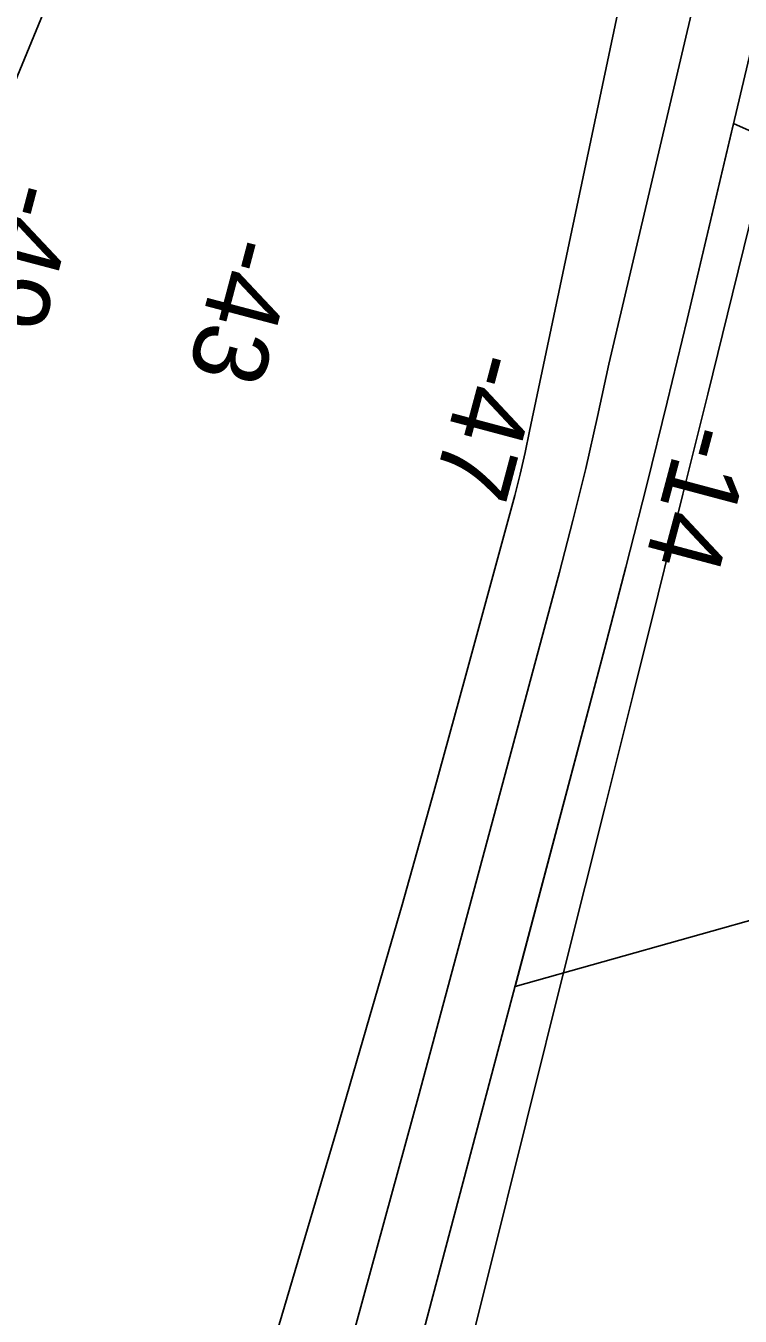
# Model space of a CAD drawing. Extents: x 3930721 to 3950824, y 220441 to 242861.
# Drawn here: x 3942447 to 3942767, y 232468 to 233046 of the extents above; entities that cross this region are included whole.
import ezdxf

# ---------------------------------------------------------------- set-up
doc = ezdxf.new("R2010")
doc.units = 0
for name, color, linetype in [('V-RIVR-RANG', 7, 'Continuous'), ('V-TOPO-DPTH', 7, 'Continuous'), ('V-TOPO-MAJR', 7, 'Continuous'), ('V-TOPO-MINR', 7, 'Continuous')]:
    doc.layers.add(name, color=color, linetype=linetype)

msp = doc.modelspace()

# ---------------------------------------------------------------- linework, layer by layer
at = {"layer": 'V-TOPO-DPTH'}
for points in [[(3942394.35, 231903.74), (3942586.24, 232551.54), (3942600.96, 232601.87), (3942615.46, 232652.28), (3942629.6, 232702.77), (3942643.52, 232753.34), (3942665.84, 232835.53), (3942668.29, 232845.07), (3942670.55, 232854.66), (3942672.53, 232864.32), (3942877.36, 233836.08), (3942881.48, 233843.98), (3943173.71, 234806.38)], [(3942394.35, 231903.74), (3942586.24, 232551.54), (3942600.96, 232601.87), (3942615.46, 232652.28), (3942629.6, 232702.77), (3942643.52, 232753.34), (3942665.84, 232835.53), (3942668.29, 232845.07), (3942670.55, 232854.66), (3942672.53, 232864.32), (3942877.36, 233836.08), (3942881.48, 233843.98), (3943173.71, 234806.38)], [(3943259.12, 234785.67), (3942961.54, 233812), (3942959.14, 233808.57), (3942932.99, 233722.43), (3942924.03, 233691.19), (3942915.71, 233659.79), (3942908.36, 233628.14), (3942901.66, 233596.34), (3942895.25, 233564.46), (3942888.58, 233532.63), (3942881.54, 233500.88), (3942874.25, 233469.19), (3942743.02, 232914.22), (3942734.11, 232877.23), (3942725.01, 232840.29), (3942715.61, 232803.43), (3942706.01, 232766.62), (3942520.88, 232068.19)], [(3942436.28, 231927.03), (3942493.1, 232113.56), (3942526.94, 232226.69), (3942560.03, 232340.04), (3942591.98, 232453.72), (3942623.16, 232567.61), (3942685.84, 232801.09), (3942691.85, 232824.28), (3942697.59, 232847.52), (3942702.93, 232870.87), (3942708.01, 232894.27), (3942928.96, 233833.41), (3943212.47, 234783.37)], [(3943212.47, 234783.37), (3942928.96, 233833.41), (3942708.01, 232894.27), (3942702.93, 232870.87), (3942697.59, 232847.52), (3942691.85, 232824.28), (3942685.84, 232801.09), (3942623.16, 232567.61), (3942591.98, 232453.72), (3942560.03, 232340.04), (3942526.94, 232226.69), (3942493.1, 232113.56), (3942436.28, 231927.03)], [(3942763.76, 233001.92), (3942941.1, 232922.74), (3942912.33, 232838.35), (3942905.07, 232816.5), (3942898.02, 232794.58), (3942891.31, 232772.57), (3942884.81, 232750.48), (3942862.06, 232670.91), (3942666.01, 232615.71)], [(3942666.01, 232615.71), (3942706.01, 232766.62), (3942715.61, 232803.43), (3942725.01, 232840.29), (3942734.11, 232877.23), (3942743.02, 232914.22), (3942763.76, 233001.92)]]:
    msp.add_lwpolyline(points, dxfattribs=at)
at = {"layer": 'V-TOPO-MAJR'}
msp.add_lwpolyline([(3942426.33, 232982.01), (3942628.93, 233474.42), (3942659.33, 233559.14), (3942689.04, 233644.11), (3942718.27, 233729.25), (3942761.15, 233855.79), (3942768.65, 233877.76), (3942776.23, 233899.7), (3943062.84, 234610.47)], dxfattribs=at)
at = {"layer": 'V-TOPO-MINR'}
for points in [[(3942394.35, 231903.74), (3942586.24, 232551.54), (3942600.96, 232601.87), (3942615.46, 232652.28), (3942629.6, 232702.77), (3942643.52, 232753.34), (3942665.84, 232835.53), (3942668.29, 232845.07), (3942670.55, 232854.66), (3942672.53, 232864.32), (3942877.36, 233836.08), (3942881.48, 233843.98), (3943173.71, 234806.38)], [(3942520.88, 232068.19), (3942706.01, 232766.62), (3942715.61, 232803.43), (3942725.01, 232840.29), (3942734.11, 232877.23), (3942743.02, 232914.22), (3942874.25, 233469.19), (3942881.54, 233500.88), (3942888.58, 233532.63), (3942895.25, 233564.46), (3942901.66, 233596.34), (3942908.36, 233628.14), (3942915.71, 233659.79), (3942924.03, 233691.19), (3942932.99, 233722.43), (3942959.14, 233808.57), (3942961.54, 233812), (3943259.12, 234785.67)], [(3942436.28, 231927.03), (3942493.1, 232113.56), (3942526.94, 232226.69), (3942560.03, 232340.04), (3942591.98, 232453.72), (3942623.16, 232567.61), (3942685.84, 232801.09), (3942691.85, 232824.28), (3942697.59, 232847.52), (3942702.93, 232870.87), (3942708.01, 232894.27), (3942928.96, 233833.41), (3943212.47, 234783.37)], [(3942636.11, 232415.04), (3942653.61, 232485.21), (3942671.11, 232555.37), (3942688.63, 232625.54), (3942706.15, 232695.7), (3942718.83, 232746.45), (3942729.99, 232791.24), (3942741.12, 232836.04), (3942752.21, 232880.85), (3942763.26, 232925.67), (3942963.52, 233739.42)]]:
    msp.add_lwpolyline(points, dxfattribs=at)

# ---------------------------------------------------------------- texts
at = {"layer": 'V-RIVR-RANG'}
for s, rotation, p in [('-49', 255.20747, (3942438.3, 232977.8)), ('-43', 255.20747, (3942536.11, 232953.4)), ('-47', 255.06833, (3942645.85, 232901.76)), ('-14', 255.06833, (3942740.74, 232869.47))]:
    msp.add_text(s, height=33.5, rotation=rotation, dxfattribs=at).set_placement(p)

doc.saveas('drawing.dxf')
